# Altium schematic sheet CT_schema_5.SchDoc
size 297 x 173 mm
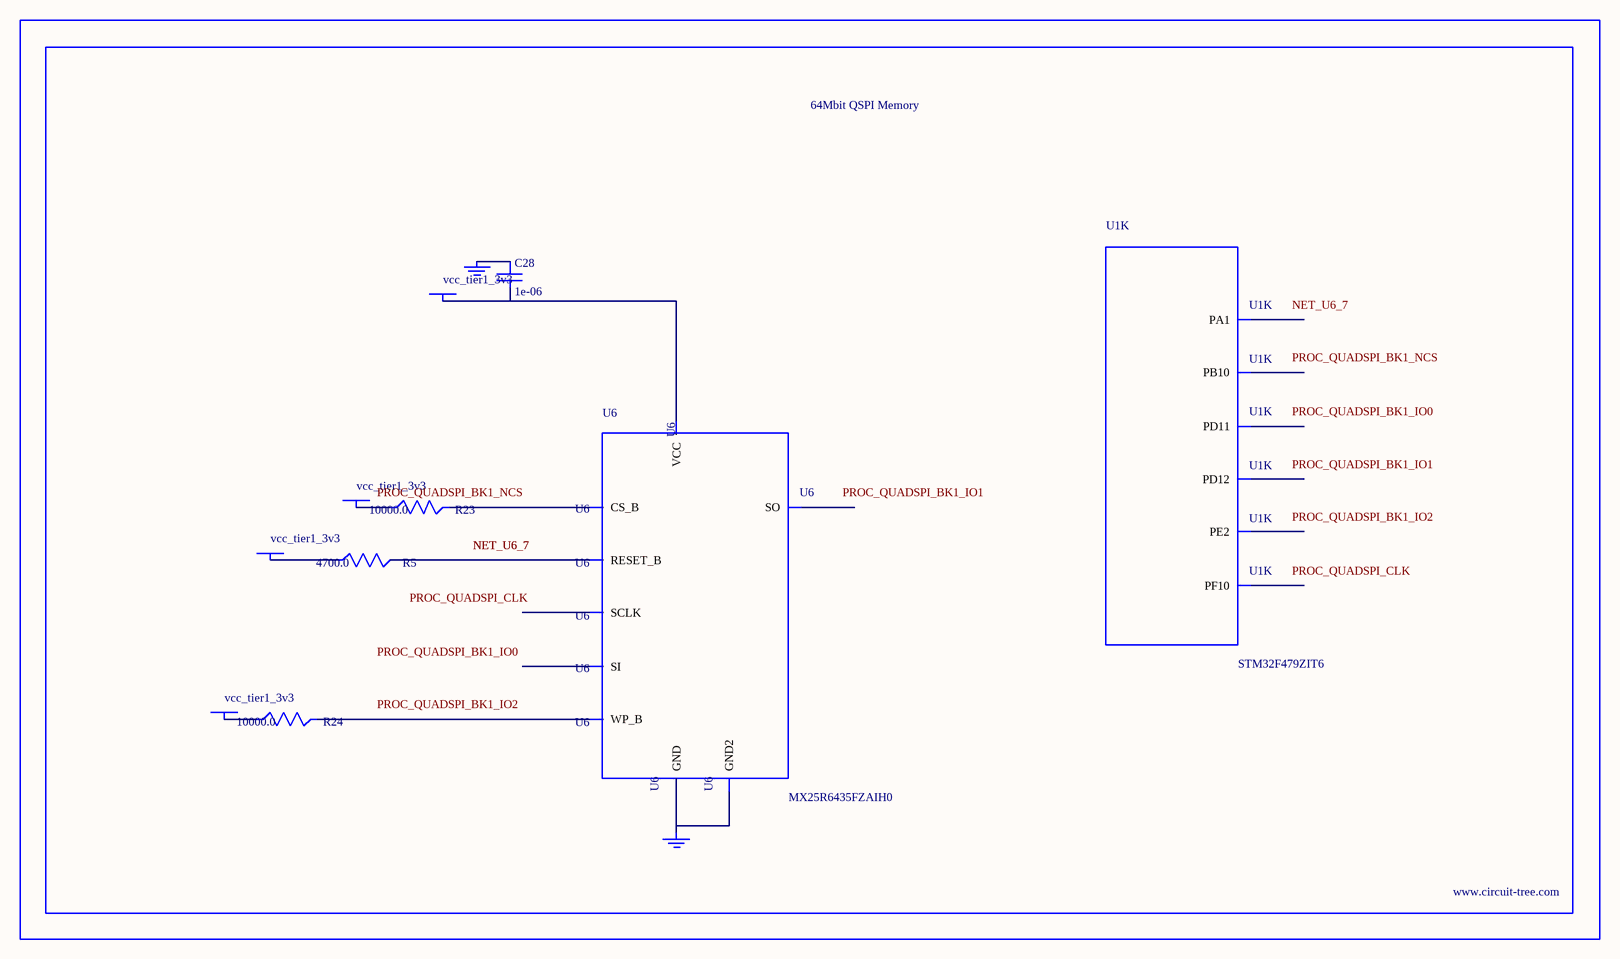
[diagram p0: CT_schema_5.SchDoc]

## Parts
BORDER4  (no value)
C28  1e-06  [C0603]
GND_INSTANCE_4_0  (no value)
GND_INSTANCE_4_1  (no value)
POWER_INSTANCE_4_0  vcc_tier1_3v3
POWER_INSTANCE_4_1  vcc_tier1_3v3
POWER_INSTANCE_4_2  vcc_tier1_3v3
POWER_INSTANCE_4_3  vcc_tier1_3v3
R5  4700.0  [R0603]
R23  10000.0  [R0603]
R24  10000.0  [R0603]
U1  STM32F479ZIT6  [LQFP144]  (part K of 13)
U6  MX25R6435FZAIH0  [WSON-8-PAD]

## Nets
NetC28_1: C28.1 GND_INSTANCE_4_0.0(GND)
NetC28_2: C28.2 POWER_INSTANCE_4_2.0(PWR) U6.8(VCC)
NetGND_INSTANCE_4_1_0: GND_INSTANCE_4_1.0(GND) U6.4(GND) U6.PAD(GND2)
NetPOWER_INSTANCE_4_0_0: POWER_INSTANCE_4_0.0(PWR) R23.1
NetPOWER_INSTANCE_4_1_0: POWER_INSTANCE_4_1.0(PWR) R24.1
NetPOWER_INSTANCE_4_3_0: POWER_INSTANCE_4_3.0(PWR) R5.1
NetR5_2: R5.2 U6.7(RESET_B)
NetR23_2: R23.2 U6.1(CS_B)
NetR24_2: R24.2 U6.3(WP_B)

Not connected (* = marked no-connect by the designer): U1 17(PF10) 30(PA1) 63(PB10) 74(PD11) 75(PD12) 144(PE2); U6 2(SO) 5(SI) 6(SCLK)

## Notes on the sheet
- Labels drawn without touching a wire or pin: NET_U6_7, PROC_QUADSPI_BK1_IO0, PROC_QUADSPI_BK1_IO1, PROC_QUADSPI_BK1_IO2, PROC_QUADSPI_BK1_NCS, PROC_QUADSPI_CLK

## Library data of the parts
BORDER4 = BORDER_PAGE4
C28 = C0603C105K3RACTU
GND_INSTANCE_4_0 GND_INSTANCE_4_1 = GND
POWER_INSTANCE_4_0-POWER_INSTANCE_4_3 = PWR
R5 = RC0603JR-074K7L
R23 R24 = RC0603JR-0710KL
